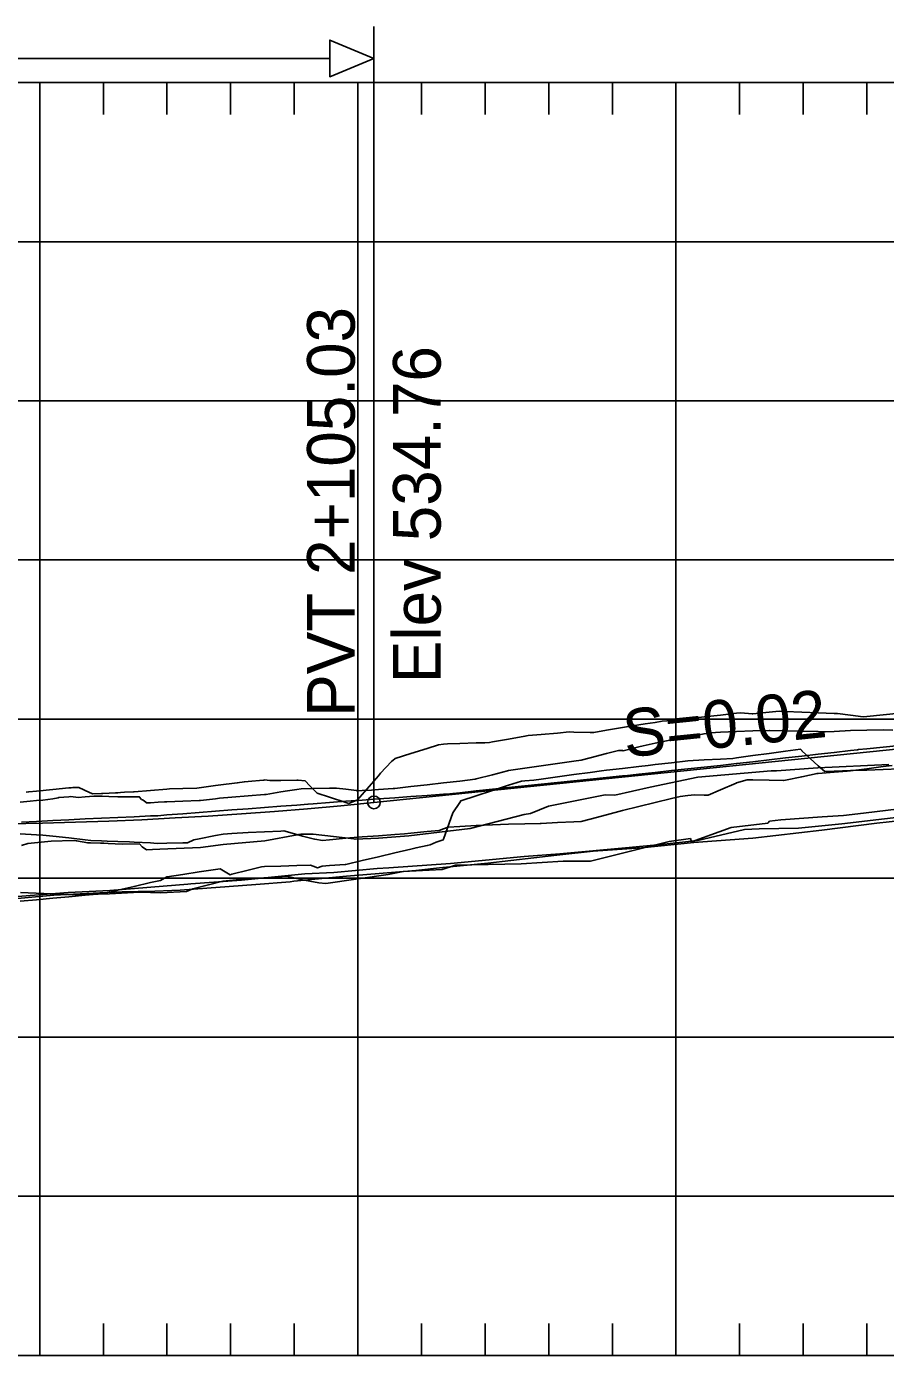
# Model space of a CAD drawing. Extents: x 704834 to 709892, y 372981 to 377533.
# Drawn here: x 707196.3 to 707466.2, y 375272.4 to 375690.1 of the extents above; entities that cross this region are included whole.
import ezdxf

# ---------------------------------------------------------------- set-up
doc = ezdxf.new("R2010")
doc.units = 0
for name, color, linetype in [('10', 7, 'Continuous'), ('12', 7, 'Continuous'), ('13', 7, 'Continuous'), ('20', 7, 'Continuous'), ('42', 7, 'Continuous'), ('49', 7, 'Continuous'), ('61', 7, 'Continuous'), ('63', 7, 'Continuous'), ('Existing', 7, 'Continuous')]:
    doc.layers.add(name, color=color, linetype=linetype)

msp = doc.modelspace()

# ---------------------------------------------------------------- linework, layer by layer
at = {"layer": '10'}
for points in [[(707467.28, 375458.16), (707444.97, 375457.06), (707431.95, 375456.18), (707431.82, 375456.15), (707431.71, 375456.17), (707431.26, 375456.15), (707430.31, 375456.17), (707407.27, 375454.15), (707392.33, 375451.03), (707381.13, 375448.54), (707378.17, 375448.67), (707360.37, 375445.1), (707354.65, 375442.78), (707352.63, 375442.46), (707335.65, 375438.01), (707316.4, 375435.77), (707306.86, 375435.04), (707299.54, 375434.66), (707299.12, 375434.81), (707286.38, 375436.27), (707282.5, 375436.27), (707281.79, 375436.17), (707281.32, 375436.09), (707271.2, 375434.18), (707258.08, 375432.98), (707250.92, 375432.12), (707238.11, 375431.56), (707235.89, 375431.43), (707233.96, 375431.32), (707233.57, 375431.66), (707233.01, 375432.01), (707232.57, 375432.24), (707231.74, 375433.24), (707226.3, 375433.16), (707226.26, 375433.16), (707221.88, 375433.35), (707220.51, 375433.42), (707219.48, 375433.47), (707216.4, 375433.53), (707215.48, 375433.52), (707211.99, 375434.19), (707211.87, 375434.18), (707210.98, 375434.26), (707204.01, 375434.04), (707203.94, 375434.01), (707196.62, 375433.32), (707194.65, 375432.74)], [(707194.35, 375417.95), (707211.49, 375417.2), (707222.34, 375417.53), (707231.75, 375418.02), (707231.99, 375418.02), (707238.44, 375417.77), (707246.58, 375418.2), (707248.5, 375419.12), (707257.99, 375421.46), (707262.12, 375421.92), (707278.05, 375423.07), (707282.45, 375422.06), (707288.16, 375420.95), (707290.32, 375420.72), (707309.92, 375423.59), (707314.63, 375424.52), (707326.88, 375425.14), (707331.07, 375426.49), (707351.72, 375426.94), (707364.89, 375427.77), (707373.51, 375427.81), (707398.29, 375433.92), (707404.96, 375434.88), (707405.3, 375433.84), (707417.74, 375438.33), (707429.22, 375439.75), (707429.83, 375440.35), (707433.35, 375440.78), (707446.36, 375441.68), (707453.03, 375442.08), (707459.29, 375442.87), (707474.03, 375444.63)]]:
    msp.add_lwpolyline(points, dxfattribs=at)
at = {"layer": '12'}
msp.add_lwpolyline([(707186.7, 375416.1), (707209.3, 375417.89), (707222.42, 375418.59), (707246.92, 375420.51), (707247.86, 375420.6), (707263.86, 375421.78), (707283.75, 375423.77), (707292.84, 375424.26), (707306.46, 375425.48), (707310.12, 375425.69), (707329.53, 375427), (707352.67, 375429.2), (707363.91, 375430.13), (707384.58, 375432), (707395.64, 375433), (707407.26, 375434.31), (707421.98, 375437.75), (707426.57, 375437.9), (707438.95, 375438.17), (707452.55, 375439.5), (707479.35, 375442.61)], dxfattribs=at)
at = {"layer": '13'}
msp.add_lwpolyline([(707482.89, 375441.82), (707463.54, 375439.72), (707446.22, 375437.54), (707424.54, 375435.05), (707406, 375433.6), (707389.57, 375432.01), (707374.36, 375430.9), (707362.94, 375429.64), (707341.24, 375427.18), (707326.01, 375425.7), (707318.61, 375424.84), (707296.81, 375423.05), (707280.32, 375421.51), (707279.14, 375421.31), (707268.29, 375420.42), (707244.53, 375418.69), (707233.97, 375418.23), (707231.51, 375418.25), (707231.38, 375418.29), (707226.3, 375418.11), (707219.27, 375417.78), (707204.83, 375417.14), (707188.84, 375415.61)], dxfattribs=at)
at = {"layer": '42'}
for q in [(707305.44, 375690.05), (707305.44, 375602.24), (707518.3, 375467.97)]:
    msp.add_line((707305.44, 375446.24), q, dxfattribs=at)
msp.add_lwpolyline([(707305.44, 375680.05), (707291.58, 375685.79), (707291.58, 375674.31)], close=True, dxfattribs=at)
for points in [[(706819.3, 375680.05), (707291.58, 375680.05)], [(707190.85, 375439.52), (707201.27, 375439.72), (707211.69, 375440), (707222.1, 375440.36), (707232.52, 375440.81), (707242.94, 375441.34), (707253.35, 375441.95), (707263.77, 375442.64), (707274.19, 375443.42), (707284.6, 375444.27), (707295.02, 375445.21), (707305.44, 375446.24)]]:
    msp.add_lwpolyline(points, dxfattribs=at)
msp.add_circle((707305.44, 375446.24), 2, dxfattribs=at)
at = {"layer": '61'}
for p, q in [((706700.4, 375672.45), (709300.4, 375672.45)), ((707200.4, 375272.45), (707200.4, 375672.45)), ((707220.4, 375672.45), (707220.4, 375662.45)), ((707240.4, 375672.45), (707240.4, 375662.45)), ((707260.4, 375672.45), (707260.4, 375662.45)), ((707280.4, 375672.45), (707280.4, 375662.45)), ((707300.4, 375272.45), (707300.4, 375672.45)), ((707320.4, 375672.45), (707320.4, 375662.45)), ((707340.4, 375672.45), (707340.4, 375662.45)), ((707360.4, 375672.45), (707360.4, 375662.45)), ((707380.4, 375672.45), (707380.4, 375662.45)), ((707400.4, 375272.45), (707400.4, 375672.45)), ((707420.4, 375672.45), (707420.4, 375662.45)), ((707440.4, 375672.45), (707440.4, 375662.45)), ((707460.4, 375672.45), (707460.4, 375662.45)), ((706700.4, 375622.45), (709300.4, 375622.45)), ((706700.4, 375572.45), (709300.4, 375572.45)), ((706700.4, 375522.45), (709300.4, 375522.45)), ((706700.4, 375472.45), (709300.4, 375472.45)), ((706700.4, 375422.45), (709300.4, 375422.45)), ((706700.4, 375372.45), (709300.4, 375372.45)), ((706700.4, 375322.45), (709300.4, 375322.45)), ((707220.4, 375272.45), (707220.4, 375282.45)), ((707240.4, 375272.45), (707240.4, 375282.45)), ((707260.4, 375272.45), (707260.4, 375282.45)), ((707280.4, 375272.45), (707280.4, 375282.45)), ((707320.4, 375272.45), (707320.4, 375282.45)), ((707340.4, 375272.45), (707340.4, 375282.45)), ((707360.4, 375272.45), (707360.4, 375282.45)), ((707380.4, 375272.45), (707380.4, 375282.45)), ((707420.4, 375272.45), (707420.4, 375282.45)), ((707440.4, 375272.45), (707440.4, 375282.45)), ((707460.4, 375272.45), (707460.4, 375282.45)), ((706700.4, 375272.45), (709300.4, 375272.45))]:
    msp.add_line(p, q, dxfattribs=at)
at = {"layer": '63'}
for points in [[(707196.1, 375449.43), (707196.92, 375449.58), (707199.36, 375449.81), (707204.48, 375450.3), (707209.59, 375450.78), (707210.27, 375450.84), (707210.85, 375450.9), (707211.06, 375450.9), (707212.04, 375450.88), (707212.66, 375450.95), (707214.27, 375450.21), (707214.71, 375449.99), (707217.02, 375448.91), (707219.83, 375449.02), (707220.06, 375449.03), (707220.2, 375449.05), (707222.27, 375449.14), (707224.16, 375449.25), (707224.95, 375449.3), (707225.77, 375449.36), (707227.06, 375449.46), (707229.9, 375449.52), (707230.07, 375449.53), (707235.19, 375449.97), (707240.31, 375450.41), (707241.22, 375450.49), (707245.42, 375450.58), (707249.79, 375450.67), (707250.54, 375450.78), (707255.66, 375451.54), (707258.16, 375451.91), (707260.78, 375452.17), (707262.5, 375452.34), (707264.75, 375452.75), (707265.9, 375452.85), (707270.62, 375453.26), (707270.72, 375453.19), (707270.8, 375453.16), (707271.02, 375453.34), (707271.07, 375453.38), (707272.76, 375453.17), (707273.68, 375453.15), (707276.14, 375453.17), (707281.25, 375453.19), (707281.68, 375453.19), (707283.83, 375452.98), (707285.28, 375451.49), (707286.37, 375450.38), (707287.61, 375449.13), (707291.49, 375447.84), (707296.61, 375446.18), (707297.53, 375445.88), (707300.24, 375447.02), (707301.73, 375448.74), (707306.85, 375454.64), (707307.5, 375455.38), (707310.94, 375459.14), (707311.97, 375459.92), (707312, 375459.94), (707312.11, 375460.06), (707317.08, 375461.62), (707322.2, 375463.22), (707325.72, 375464.31), (707327.32, 375464.5), (707328.59, 375464.65), (707332.44, 375464.76), (707337.56, 375464.92), (707340.31, 375465), (707341.82, 375465.08), (707342.68, 375465.23), (707347.8, 375466.14), (707352.91, 375467.04), (707353.9, 375467.22), (707358.03, 375467.59), (707363.15, 375468.05), (707366.84, 375468.39), (707368.27, 375468.36), (707373.39, 375468.26), (707374.57, 375468.23), (707378.51, 375468.89), (707383.63, 375469.75), (707388.74, 375470.6), (707390.73, 375470.93), (707393.86, 375471.4), (707396.05, 375471.72), (707398.98, 375472.03), (707404.1, 375472.56), (707404.96, 375472.65), (707409.22, 375473.12), (707414.34, 375473.68), (707419.46, 375474.24), (707420.82, 375474.39), (707424.37, 375474.05), (707424.57, 375474.07), (707429.69, 375474.57), (707432.81, 375474.87), (707434.81, 375474.79), (707439.93, 375474.59), (707445.05, 375474.39), (707450.17, 375474.2), (707451.16, 375474.16), (707455.29, 375473.62), (707459.24, 375473.11), (707460.4, 375473.23), (707465.52, 375473.75), (707470.64, 375474.26)], [(707194.24, 375446.33), (707197.38, 375446.66), (707199.36, 375446.79), (707201.39, 375446.91), (707204.48, 375447.4), (707206.23, 375447.67), (707206.36, 375447.74), (707209.59, 375448.01), (707210.13, 375448.05), (707212.51, 375447.8), (707214.66, 375447.96), (707214.71, 375447.96), (707217.44, 375448.17), (707219.83, 375448.17), (707219.97, 375448.17), (707222.14, 375448.1), (707224.95, 375447.99), (707225.6, 375447.97), (707227.24, 375447.94), (707230.07, 375447.99), (707231.7, 375448.02), (707232.38, 375447.19), (707232.75, 375447), (707233.22, 375446.71), (707233.83, 375446.19), (707233.92, 375446.07), (707234.57, 375446.11), (707235.19, 375446.14), (707237.67, 375446.28), (707239.63, 375446.39), (707240.31, 375446.42), (707245.42, 375446.63), (707250.54, 375446.84), (707250.91, 375446.85), (707255.66, 375447.39), (707256.94, 375447.53), (707260.78, 375447.85), (707265.9, 375448.27), (707271.02, 375448.68), (707271.53, 375448.72), (707276.14, 375449.52), (707278.29, 375449.89), (707281.25, 375450.34), (707282.56, 375450.54), (707286.37, 375450.61), (707291.49, 375450.7), (707293.7, 375450.73), (707296.61, 375450.37), (707299.94, 375449.97), (707300.18, 375449.88), (707301.73, 375449.96), (707304.71, 375450.1), (707306.85, 375450.25), (707311.54, 375450.59), (707311.97, 375450.63), (707317.08, 375451.19), (707322.2, 375451.77), (707327.32, 375452.35), (707332.44, 375452.95), (707337.22, 375453.52), (707337.56, 375453.6), (707342.68, 375454.95), (707347.4, 375456.2), (707347.8, 375456.26), (707352.91, 375457.01), (707358.03, 375457.74), (707363.15, 375458.46), (707368.27, 375459.17), (707370.56, 375459.48), (707373.39, 375460.26), (707378.51, 375461.59), (707382.32, 375462.53), (707383.63, 375462.5), (707383.81, 375462.49), (707388.74, 375463.71), (707390.11, 375464.02), (707393.86, 375464.85), (707398.98, 375465.9), (707404.1, 375466.88), (707409.22, 375467.79), (707411.2, 375468.12), (707414.34, 375468.29), (707419.46, 375468.52), (707424.57, 375468.69), (707429.69, 375468.81), (707429.84, 375468.81), (707434.81, 375468.76), (707439.93, 375468.66), (707445.05, 375468.5), (707447.54, 375468.4), (707450.17, 375468.57), (707455.29, 375468.82), (707460.4, 375468.96), (707465.52, 375469.01), (707468.57, 375468.98)], [(707194.24, 375415.19), (707199.36, 375415.67), (707204.48, 375416.14), (707209.59, 375416.6), (707214.71, 375417.05), (707219.83, 375417.49), (707219.98, 375417.5), (707224.95, 375418.66), (707230.07, 375419.85), (707235.19, 375421.03), (707238.31, 375421.74), (707240.31, 375422.81), (707240.41, 375422.87), (707245.42, 375423.61), (707250.54, 375424.38), (707255.66, 375425.14), (707257.14, 375425.36), (707260.25, 375423.53), (707260.78, 375423.66), (707265.9, 375424.95), (707270.14, 375426.03), (707271.02, 375426.06), (707276.14, 375426.21), (707281.25, 375426.39), (707285.52, 375426.56), (707286.37, 375426.2), (707287.69, 375425.65), (707289.2, 375426.23), (707291.49, 375426.38), (707296.43, 375426.73), (707296.61, 375426.77), (707301.73, 375427.94), (707306.85, 375429.13), (707311.97, 375430.34), (707317.08, 375431.58), (707318.7, 375431.98), (707322.2, 375432.69), (707323.11, 375432.88), (707325, 375433.78), (707327.25, 375434.45), (707327.32, 375434.64), (707330.2, 375442.97), (707332.44, 375446.26), (707332.77, 375446.77), (707337.56, 375448.31), (707342.68, 375449.97), (707347.8, 375451.63), (707351.8, 375452.93), (707352.91, 375453.03), (707355.76, 375453.26), (707358.03, 375453.57), (707363.15, 375454.27), (707368.27, 375454.96), (707373.39, 375455.65), (707376.95, 375456.13), (707378.51, 375456.32), (707383.63, 375456.92), (707388.74, 375457.52), (707391.62, 375457.85), (707393.86, 375458.11), (707398.98, 375458.7), (707404.1, 375459.28), (707404.16, 375459.28), (707409.22, 375459.57), (707414.34, 375459.85), (707418.29, 375460.07), (707419.46, 375460.23), (707424.57, 375460.93), (707429.69, 375461.62), (707434.81, 375462.31), (707439.59, 375462.93), (707439.93, 375462.5), (707439.97, 375462.45), (707445.05, 375457.76), (707447.15, 375455.91), (707450.17, 375456.01), (707455.29, 375456.22), (707458.25, 375456.36), (707460.4, 375456.42), (707465.52, 375456.59), (707470.64, 375456.81)], [(707194.24, 375436.32), (707199.36, 375436.08), (707201.33, 375435.98), (707204.48, 375435.66), (707209.59, 375435.09), (707214.71, 375434.48), (707216.45, 375434.26), (707219.83, 375434.13), (707221.59, 375434.06), (707224.95, 375433.98), (707228.57, 375433.87), (707230.07, 375433.79), (707235.19, 375433.5), (707237.32, 375433.37), (707240.31, 375433.44), (707245.42, 375433.54), (707246.82, 375433.56), (707248.83, 375434.46), (707250.54, 375434.82), (707255.66, 375435.84), (707258.1, 375436.31), (707260.78, 375436.47), (707265.9, 375436.75), (707271.02, 375437.01), (707276.14, 375437.23), (707277.17, 375437.27), (707281.25, 375436.13), (707282.97, 375435.64), (707286.37, 375434.79), (707286.84, 375434.67), (707289.23, 375434.27), (707291.49, 375434.49), (707296.61, 375434.95), (707301.73, 375435.38), (707306.85, 375435.77), (707311.97, 375436.13), (707315.05, 375436.33), (707317.08, 375436.55), (707322.2, 375437.07), (707325.96, 375437.42), (707327.32, 375437.9), (707328.8, 375438.43), (707332.44, 375438.66), (707337.56, 375438.94), (707342.68, 375439.18), (707347.8, 375439.38), (707352.91, 375439.53), (707357.69, 375439.64), (707358.03, 375439.66), (707363.15, 375439.95), (707368.27, 375440.18), (707370.6, 375440.27), (707373.39, 375441.02), (707378.51, 375442.37), (707383.63, 375443.68), (707388.74, 375444.96), (707393.86, 375446.21), (707398.98, 375447.43), (707401.76, 375448.07), (707404.1, 375448.37), (707406.21, 375448.64), (707409.22, 375448.55), (707410.5, 375448.51), (707414.34, 375450.18), (707419.27, 375452.31), (707419.46, 375452.37), (707422.73, 375453.34), (707424.57, 375453.31), (707429.69, 375453.21), (707434.23, 375453.12), (707434.81, 375453.24), (707439.93, 375454.32), (707444.75, 375455.33), (707445.05, 375455.35), (707450.17, 375455.72), (707454.26, 375456.01), (707455.29, 375456.15), (707460.4, 375456.83), (707465.52, 375457.49), (707468.32, 375457.84)]]:
    msp.add_lwpolyline(points, dxfattribs=at)
at = {"layer": 'Existing'}
msp.add_lwpolyline([(707194.63, 375440.02), (707199.36, 375440.27), (707204.48, 375440.53), (707209.59, 375440.78), (707214.71, 375441.03), (707219.83, 375441.28), (707224.95, 375441.52), (707230.07, 375441.75), (707235.19, 375441.97), (707236.23, 375442.02), (707236.8, 375442.04), (707236.8, 375442.04), (707236.92, 375442.04), (707237.48, 375442.07), (707240.31, 375442.3), (707245.42, 375442.7), (707250.54, 375443.1), (707255.66, 375443.5), (707260.78, 375443.89), (707265.9, 375444.27), (707271.02, 375444.65), (707276.14, 375445.03), (707281.25, 375445.4), (707284.68, 375445.64), (707284.71, 375445.64), (707284.72, 375445.64), (707284.77, 375445.65), (707286.37, 375445.78), (707291.49, 375446.18), (707296.61, 375446.58), (707301.73, 375446.96), (707306.85, 375447.34), (707311.97, 375447.72), (707317.08, 375448.08), (707322.2, 375448.44), (707327.32, 375448.79), (707329.32, 375448.92), (707330.29, 375449.02), (707332.44, 375449.26), (707337.56, 375449.83), (707342.68, 375450.39), (707347.8, 375450.94), (707352.91, 375451.48), (707358.03, 375452.01), (707363.15, 375452.54), (707368.27, 375453.05), (707373.39, 375453.56), (707378.51, 375454.06), (707383.63, 375454.55), (707383.93, 375454.57), (707385.18, 375454.69), (707388.74, 375455.1), (707393.86, 375455.67), (707398.98, 375456.24), (707404.1, 375456.8), (707409.22, 375457.35), (707414.34, 375457.89), (707419.41, 375458.42), (707419.46, 375458.42), (707419.57, 375458.43), (707424.57, 375459.02), (707429.69, 375459.63), (707434.81, 375460.22), (707439.93, 375460.81), (707445.05, 375461.39), (707450.17, 375461.97), (707455.29, 375462.54), (707457.49, 375462.78), (707457.81, 375462.82), (707460.4, 375463.09), (707465.52, 375463.61), (707470.64, 375464.12)], dxfattribs=at)

# ---------------------------------------------------------------- texts
at = {"layer": '20'}
msp.add_text('S=0.02', height=15, rotation=5.8307, dxfattribs=at).set_placement((707384.49, 375460.34))
at = {"layer": '49'}
for s, p in [('PVT 2+105.03', (707299.44, 375473.13)), ('Elev 534.76', (707326.44, 375483.71))]:
    msp.add_text(s, height=15, rotation=90, dxfattribs=at).set_placement(p)

doc.saveas('drawing.dxf')
